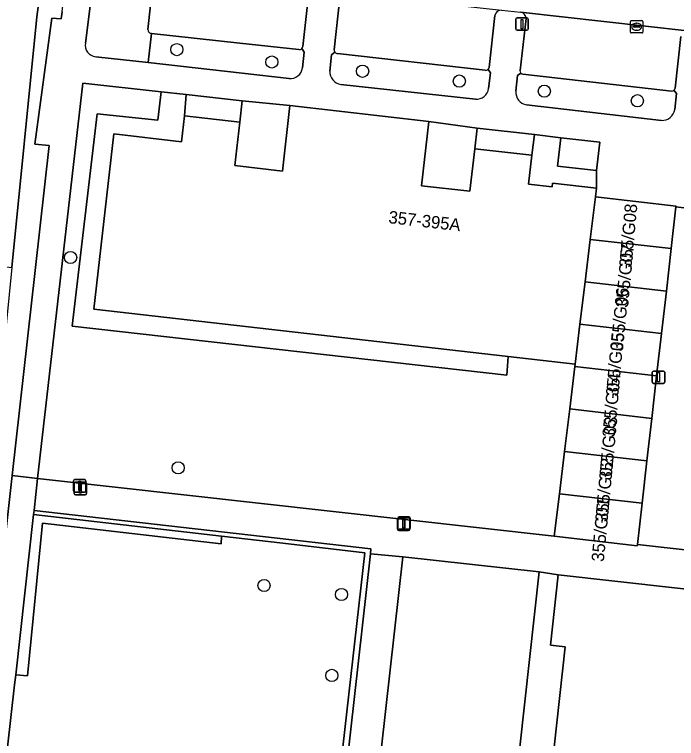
# Model space of a CAD drawing. Extents: x 161928 to 163071, y 386474 to 387428.
# Drawn here: x 162005.2 to 162058.3, y 386750.7 to 386808.8 of the extents above; entities that cross this region are included whole.
import ezdxf

# ---------------------------------------------------------------- set-up
doc = ezdxf.new("R2010")
doc.units = 0
for name, color, linetype in [('IMGEO_Berm_groen', 7, 'Continuous'), ('IMGEO_Boom', 7, 'Continuous'), ('IMGEO_Erf', 7, 'Continuous'), ('IMGEO_Groenvoorziening', 7, 'Continuous'), ('IMGEO_Haag', 7, 'Continuous'), ('IMGEO_Kolk', 7, 'Continuous'), ('IMGEO_Lichtmast', 7, 'Continuous'), ('IMGEO_Pand', 7, 'Continuous'), ('IMGEO_Pand_nummerreeks', 7, 'Continuous'), ('IMGEO_Parkeervlak_open', 7, 'Continuous'), ('IMGEO_Rijbaan_lokaal_open', 7, 'Continuous'), ('IMGEO_Voetpad_open', 7, 'Continuous')]:
    doc.layers.add(name, color=color, linetype=linetype)

msp = doc.modelspace()

# ---------------------------------------------------------------- linework, layer by layer
at = {"layer": 'IMGEO_Berm_groen'}
msp.add_lwpolyline([(162000, 386876.945), (161990.392, 386790.363), (162005.008, 386788.518), (162007.001, 386808.617), (162009.798, 386829.325)], dxfattribs=at)
at = {"layer": 'IMGEO_Boom'}
for centre in [(162018.233, 386805.998), (162025.846, 386805.003), (162033.13, 386804.262), (162040.888, 386803.474), (162047.706, 386802.66), (162055.171, 386801.897), (162009.707, 386789.308), (162018.339, 386772.436), (162025.225, 386762.991), (162031.439, 386762.26), (162030.664, 386755.77)]:
    msp.add_circle(centre, 0.489, dxfattribs=at)
at = {"layer": 'IMGEO_Erf'}
for points in [[(162016.97, 386802.618), (162016.705, 386800.327), (162011.83, 386800.848), (162009.846, 386783.804), (162044.709, 386779.862), (162044.806, 386781.365), (162011.56, 386785.17), (162013.168, 386799.23), (162018.607, 386798.607), (162018.845, 386800.686), (162018.982, 386802.396)], [(162044.512, 386725.13), (162045.14, 386730.766), (162046.333, 386730.634), (162047.268, 386739.022), (162046.075, 386739.154), (162047.261, 386749.807), (162048.454, 386749.675), (162048.49, 386750), (162049.389, 386758.073), (162048.195, 386758.205), (162048.824, 386763.85), (162047.299, 386764.081), (162045.743, 386750), (162043.01, 386725.268)]]:
    msp.add_lwpolyline(points, close=True, dxfattribs=at)
at = {"layer": 'IMGEO_Groenvoorziening'}
for points in [[(162007.994, 386798.293), (162006.852, 386798.42), (162008.208, 386808.516), (162008.959, 386808.465), (162009.031, 386809.044), (162011.288, 386829.156), (162009.798, 386829.325), (162007.001, 386808.617), (162005.008, 386788.518), (161998.505, 386722.956), (161997.23, 386714.781), (161996.045, 386706.635), (161994.485, 386698.645), (161994.672, 386692.84), (161993.174, 386677.984), (161990.334, 386655.356), (161991.413, 386650.255), (161998.872, 386716.846), (162005.028, 386771.813), (162006.873, 386788.282)], [(162050.178, 386780.75), (162044.806, 386781.365), (162044.709, 386779.862), (162009.846, 386783.804), (162011.83, 386800.848), (162016.705, 386800.327), (162016.97, 386802.618), (162010.678, 386803.312), (162007.061, 386771.581), (162048.503, 386766.944), (162048.916, 386770.347), (162049.329, 386773.751), (162049.742, 386777.154), (162050.155, 386780.557)], [(162023.281, 386800.178), (162023.483, 386801.899), (162018.982, 386802.396), (162018.845, 386800.686)], [(162046.716, 386797.515), (162046.91, 386799.189), (162042.308, 386799.694), (162042.13, 386798.04)], [(162052.172, 386798.582), (162049.03, 386798.931), (162048.771, 386796.639), (162051.904, 386796.301)], [(162021.82, 386766.942), (162006.74, 386768.689), (162005.304, 386755.813), (162006.241, 386755.742), (162007.448, 386767.992), (162021.773, 386766.325)], [(162031.554, 386750), (162033.319, 386765.609), (162026.736, 386766.372), (162021.82, 386766.942), (162021.773, 386766.325), (162007.448, 386767.992), (162006.241, 386755.742), (162005.304, 386755.813), (162005.214, 386755.021), (162004.653, 386750), (162000.921, 386716.619), (162027.442, 386713.619), (162028.943, 386726.903)], [(162045.743, 386750), (162047.299, 386764.081), (162036.361, 386765.29), (162034.645, 386750), (162032.012, 386726.545), (162033.433, 386726.38), (162043.01, 386725.268)]]:
    msp.add_lwpolyline(points, close=True, dxfattribs=at)
for points in [[(162013.294, 386825.483), (162010.901, 386806.52)], [(162015.903, 386807.622), (162016.297, 386811.299)], [(162011.721, 386805.431), (162015.927, 386804.959), (162016.195, 386807.293), (162016.142, 386807.299)], [(162028.006, 386806.003), (162023.27, 386806.52), (162016.195, 386807.293), (162015.927, 386804.959), (162027.227, 386803.691)], [(162028.307, 386804.547), (162028.431, 386805.806), (162028.255, 386806.082)], [(162030.906, 386805.784), (162030.629, 386805.593), (162030.499, 386804.276)], [(162042.95, 386804.339), (162031.119, 386805.682)], [(162043.236, 386802.887), (162043.378, 386804.136), (162043.19, 386804.405)], [(162045.82, 386804.117), (162045.564, 386803.928), (162045.434, 386802.677)], [(162057.906, 386802.677), (162045.987, 386804.016)], [(162031.388, 386803.21), (162042.177, 386802.029)], [(162058.164, 386801.204), (162058.308, 386802.479), (162058.103, 386802.744)], [(162046.266, 386801.556), (162057.102, 386800.316)]]:
    msp.add_lwpolyline(points, dxfattribs=at)
for centre, radius, start, end in [((162016.247, 386807.627), 0.344, 180.7708, 252.2275), ((162011.803, 386806.346), 0.919, 169.08634, 264.87201), ((162028.052, 386806.29), 0.291, 260.90676, 314.29849), ((162031.123, 386805.964), 0.282, 219.67341, 269.14956), ((162027.349, 386804.646), 0.963, 262.6966, 354.10356), ((162031.509, 386804.215), 1.012, 176.5187, 263.13473), ((162042.997, 386804.636), 0.301, 260.96096, 309.79155), ((162046.046, 386804.302), 0.292, 219.29109, 258.37861), ((162042.266, 386803.002), 0.977, 264.79074, 353.23793), ((162046.457, 386802.567), 1.029, 173.84566, 259.31954), ((162057.907, 386802.997), 0.32, 269.8028, 307.7637), ((162057.158, 386801.328), 1.013, 266.81003, 352.99189)]:
    msp.add_arc(centre, radius, start, end, dxfattribs=at)
at = {"layer": 'IMGEO_Haag'}
for points in [[(162023.281, 386800.178), (162023.483, 386801.899), (162018.982, 386802.396), (162018.845, 386800.686)], [(162046.716, 386797.515), (162046.91, 386799.189), (162042.308, 386799.694), (162042.13, 386798.04)], [(162052.172, 386798.582), (162049.03, 386798.931), (162048.771, 386796.639), (162051.904, 386796.301)], [(162021.82, 386766.942), (162006.74, 386768.689), (162005.304, 386755.813), (162006.241, 386755.742), (162007.448, 386767.992), (162021.773, 386766.325)]]:
    msp.add_lwpolyline(points, close=True, dxfattribs=at)
at = {"layer": 'IMGEO_Kolk'}
for p, q in [((162054.611, 386807.41), (162054.611, 386808.262)), ((162054.686, 386808.336), (162055.538, 386808.336)), ((162055.612, 386808.262), (162055.612, 386807.41)), ((162054.87, 386807.83), (162054.87, 386807.842)), ((162055.308, 386807.793), (162054.91, 386807.793)), ((162054.913, 386807.879), (162055.311, 386807.879)), ((162055.099, 386808.116), (162055.124, 386808.116)), ((162055.354, 386807.842), (162055.354, 386807.83)), ((162055.538, 386807.336), (162054.686, 386807.336)), ((162055.122, 386807.556), (162055.097, 386807.556))]:
    msp.add_line(p, q, dxfattribs=at)
for points in [[(162054.611, 386807.41), (162054.611, 386808.262)], [(162054.686, 386808.336), (162055.538, 386808.336)], [(162055.612, 386808.262), (162055.612, 386807.41)], [(162055.538, 386807.336), (162054.686, 386807.336)]]:
    msp.add_lwpolyline(points, dxfattribs=at)
for centre, radius, start, end in [((162054.688, 386808.26), 0.0765, 91.55205, 178.44795), ((162054.688, 386808.26), 0.0765, 91.55205, 178.44795), ((162055.536, 386808.26), 0.0765, 1.55205, 88.44795), ((162055.536, 386808.26), 0.0765, 1.55205, 88.44795), ((162054.91, 386807.839), 0.0403, 85.87752, 175.75265), ((162054.907, 386807.829), 0.0366, 178.93798, 274.71019), ((162055.311, 386807.836), 0.043, 264.86636, 352.45326), ((162055.315, 386807.841), 0.0386, 1.73085, 96.63898), ((162054.688, 386807.412), 0.0765, 181.55205, 268.44795), ((162054.688, 386807.412), 0.0765, 181.55205, 268.44795), ((162055.536, 386807.412), 0.0765, 271.55205, 358.44795), ((162055.536, 386807.412), 0.0765, 271.55205, 358.44795)]:
    msp.add_arc(centre, radius, start, end, dxfattribs=at)
for centre, major_axis, ratio, start_param, end_param in [((162055.098, 386807.836), (-0.387, 0.002), 0.722429, 4.712389, 7.853982), ((162055.123, 386807.836), (-0.39, 0.002), 0.717154, 1.570796, 4.712389)]:
    msp.add_ellipse(centre, major_axis=major_axis, ratio=ratio, start_param=start_param, end_param=end_param, dxfattribs=at)
at = {"layer": 'IMGEO_Lichtmast'}
for p, q in [((162045.426, 386807.652), (162045.426, 386808.452)), ((162045.426, 386808.452), (162045.426, 386807.652)), ((162045.526, 386808.552), (162046.316, 386808.552)), ((162046.316, 386808.552), (162045.526, 386808.552)), ((162046.416, 386808.452), (162046.416, 386807.652)), ((162046.416, 386807.652), (162046.416, 386808.452)), ((162046.316, 386807.552), (162045.526, 386807.552)), ((162045.526, 386807.552), (162046.316, 386807.552)), ((162056.37, 386779.302), (162056.37, 386780.102)), ((162056.37, 386780.102), (162056.37, 386779.302)), ((162056.47, 386780.202), (162057.26, 386780.202)), ((162057.26, 386780.202), (162056.47, 386780.202)), ((162057.36, 386780.102), (162057.36, 386779.302)), ((162057.36, 386779.302), (162057.36, 386780.102)), ((162057.26, 386779.202), (162056.47, 386779.202)), ((162056.47, 386779.202), (162057.26, 386779.202)), ((162009.938, 386770.583), (162009.938, 386771.383)), ((162009.938, 386771.383), (162009.938, 386770.583)), ((162009.999, 386770.373), (162009.999, 386771.173)), ((162009.999, 386771.173), (162009.999, 386770.373)), ((162010.038, 386771.483), (162010.828, 386771.483)), ((162010.828, 386771.483), (162010.038, 386771.483)), ((162010.099, 386771.273), (162010.889, 386771.273)), ((162010.889, 386771.273), (162010.099, 386771.273)), ((162010.928, 386771.383), (162010.928, 386770.583)), ((162010.928, 386770.583), (162010.928, 386771.383)), ((162010.989, 386771.173), (162010.989, 386770.373)), ((162010.989, 386770.373), (162010.989, 386771.173)), ((162010.828, 386770.483), (162010.038, 386770.483)), ((162010.038, 386770.483), (162010.828, 386770.483)), ((162010.889, 386770.273), (162010.099, 386770.273)), ((162010.099, 386770.273), (162010.889, 386770.273)), ((162035.925, 386767.512), (162035.925, 386768.312)), ((162035.925, 386768.312), (162035.925, 386767.512)), ((162035.958, 386767.597), (162035.958, 386768.397)), ((162035.958, 386768.397), (162035.958, 386767.597)), ((162036.025, 386768.412), (162036.815, 386768.412)), ((162036.815, 386768.412), (162036.025, 386768.412)), ((162036.058, 386768.497), (162036.848, 386768.497)), ((162036.848, 386768.497), (162036.058, 386768.497)), ((162036.915, 386768.312), (162036.915, 386767.512)), ((162036.915, 386767.512), (162036.915, 386768.312)), ((162036.948, 386768.397), (162036.948, 386767.597)), ((162036.948, 386767.597), (162036.948, 386768.397)), ((162036.848, 386767.497), (162036.058, 386767.497)), ((162036.058, 386767.497), (162036.848, 386767.497)), ((162036.815, 386767.412), (162036.025, 386767.412)), ((162036.025, 386767.412), (162036.815, 386767.412))]:
    msp.add_line(p, q, dxfattribs=at)
for points in [[(162045.846, 386808.427), (162045.996, 386808.427), (162045.996, 386807.677), (162045.846, 386807.677), (162045.846, 386808.427)], [(162056.79, 386780.077), (162056.94, 386780.077), (162056.94, 386779.327), (162056.79, 386779.327), (162056.79, 386780.077)], [(162010.358, 386771.358), (162010.508, 386771.358), (162010.508, 386770.608), (162010.358, 386770.608), (162010.358, 386771.358)], [(162010.419, 386771.148), (162010.569, 386771.148), (162010.569, 386770.398), (162010.419, 386770.398), (162010.419, 386771.148)], [(162036.345, 386768.287), (162036.495, 386768.287), (162036.495, 386767.537), (162036.345, 386767.537), (162036.345, 386768.287)], [(162036.378, 386768.372), (162036.528, 386768.372), (162036.528, 386767.622), (162036.378, 386767.622), (162036.378, 386768.372)]]:
    msp.add_lwpolyline(points, dxfattribs=at)
for centre, start, end in [((162045.526, 386808.452), 90, 180), ((162045.526, 386808.452), 90, 180), ((162046.316, 386808.452), 0, 90), ((162046.316, 386808.452), 360, 90), ((162045.526, 386807.652), 180, 270), ((162045.526, 386807.652), 180, 270), ((162046.316, 386807.652), 270, 0), ((162046.316, 386807.652), 270, 0), ((162056.47, 386780.102), 90, 180), ((162056.47, 386780.102), 90, 180), ((162057.26, 386780.102), 0, 90), ((162057.26, 386780.102), 360, 90), ((162056.47, 386779.302), 180, 270), ((162056.47, 386779.302), 180, 270), ((162057.26, 386779.302), 270, 0), ((162057.26, 386779.302), 270, 0), ((162010.038, 386771.383), 90, 180), ((162010.038, 386771.383), 90, 180), ((162010.099, 386771.173), 90, 180), ((162010.099, 386771.173), 90, 180), ((162010.828, 386771.383), 0, 90), ((162010.828, 386771.383), 360, 90), ((162010.889, 386771.173), 0, 90), ((162010.889, 386771.173), 360, 90), ((162010.038, 386770.583), 180, 270), ((162010.038, 386770.583), 180, 270), ((162010.099, 386770.373), 180, 270), ((162010.099, 386770.373), 180, 270), ((162010.828, 386770.583), 270, 0), ((162010.828, 386770.583), 270, 0), ((162010.889, 386770.373), 270, 0), ((162010.889, 386770.373), 270, 0), ((162036.025, 386768.312), 90, 180), ((162036.025, 386768.312), 90, 180), ((162036.058, 386768.397), 90, 180), ((162036.058, 386768.397), 90, 180), ((162036.815, 386768.312), 0, 90), ((162036.815, 386768.312), 360, 90), ((162036.848, 386768.397), 0, 90), ((162036.848, 386768.397), 360, 90), ((162036.025, 386767.512), 180, 270), ((162036.025, 386767.512), 180, 270), ((162036.058, 386767.597), 180, 270), ((162036.058, 386767.597), 180, 270), ((162036.815, 386767.512), 270, 0), ((162036.815, 386767.512), 270, 0), ((162036.848, 386767.597), 270, 0), ((162036.848, 386767.597), 270, 0)]:
    msp.add_arc(centre, 0.1, start, end, dxfattribs=at)
at = {"layer": 'IMGEO_Pand'}
for points in [[(162050.978, 386787.364), (162051.389, 386790.754), (162051.802, 386794.17), (162051.886, 386794.866), (162048.36, 386795.27), (162048.326, 386794.973), (162046.449, 386795.188), (162046.716, 386797.515), (162042.13, 386798.04), (162041.739, 386794.629), (162037.848, 386795.074), (162038.44, 386800.239), (162027.307, 386801.514), (162026.705, 386796.253), (162022.881, 386796.691), (162023.281, 386800.178), (162018.845, 386800.686), (162018.607, 386798.607), (162013.168, 386799.23), (162011.56, 386785.17), (162044.806, 386781.365), (162050.178, 386780.75), (162050.566, 386783.96)], [(162058.268, 386793.375), (162058.274, 386793.43), (162051.802, 386794.17), (162051.389, 386790.754), (162057.884, 386790.024)], [(162057.884, 386790.024), (162051.389, 386790.754), (162050.978, 386787.364), (162057.495, 386786.618)], [(162050.566, 386783.96), (162057.105, 386783.212), (162057.495, 386786.618), (162050.978, 386787.364)], [(162050.155, 386780.557), (162056.716, 386779.806), (162057.105, 386783.212), (162050.566, 386783.96), (162050.178, 386780.75)], [(162049.742, 386777.154), (162056.326, 386776.401), (162056.716, 386779.806), (162050.155, 386780.557)], [(162049.329, 386773.751), (162055.936, 386772.995), (162056.326, 386776.401), (162049.742, 386777.154)], [(162048.916, 386770.347), (162055.547, 386769.589), (162055.936, 386772.995), (162049.329, 386773.751)], [(162055.547, 386769.589), (162048.916, 386770.347), (162048.503, 386766.944), (162055.157, 386766.183), (162055.168, 386766.28)]]:
    msp.add_lwpolyline(points, close=True, dxfattribs=at)
msp.add_lwpolyline([(162062.945, 386762.278), (162048.824, 386763.85), (162048.195, 386758.205), (162049.389, 386758.073), (162048.49, 386750), (162048.454, 386749.675), (162047.261, 386749.807), (162046.075, 386739.154), (162047.268, 386739.022), (162046.333, 386730.634), (162045.14, 386730.766), (162044.512, 386725.13), (162058.594, 386723.562)], dxfattribs=at)
at = {"layer": 'IMGEO_Parkeervlak_open'}
for points in [[(162016.297, 386811.299), (162015.903, 386807.622)], [(162028.339, 386806.25), (162028.786, 386810.378)], [(162031.308, 386810.179), (162030.839, 386805.986)], [(162043.291, 386804.571), (162043.746, 386808.744)], [(162059.177, 386807.503), (162045.806, 386809.001)], [(162046.244, 386808.485), (162045.756, 386804.319)], [(162016.142, 386807.299), (162016.195, 386807.293), (162023.27, 386806.52), (162028.006, 386806.003)], [(162058.211, 386802.899), (162058.654, 386807.065)], [(162031.119, 386805.682), (162042.95, 386804.339)], [(162045.987, 386804.016), (162057.906, 386802.677)]]:
    msp.add_lwpolyline(points, dxfattribs=at)
for centre, radius, start, end in [((162044.231, 386808.667), 0.491, 84.80445, 171.02046), ((162045.736, 386808.497), 0.509, 358.60957, 82.0421), ((162016.247, 386807.627), 0.344, 180.7708, 252.2275), ((162028.052, 386806.29), 0.291, 260.90676, 314.29849), ((162028.052, 386806.289), 0.29, 314.5103, 352.35959), ((162031.122, 386805.968), 0.284, 176.32026, 220.37937), ((162031.123, 386805.964), 0.282, 219.67341, 269.14956), ((162042.997, 386804.636), 0.301, 260.96096, 309.79155), ((162042.99, 386804.64), 0.309, 310.33336, 347.03115), ((162046.047, 386804.3), 0.292, 176.27829, 218.88141), ((162046.046, 386804.302), 0.292, 219.29109, 258.37861), ((162057.907, 386802.997), 0.32, 269.8028, 307.7637), ((162057.914, 386802.991), 0.311, 307.43483, 342.82959)]:
    msp.add_arc(centre, radius, start, end, dxfattribs=at)
at = {"layer": 'IMGEO_Rijbaan_lokaal_open'}
for points in [[(162014.294, 386812.462), (162015.464, 386812.349), (162029.305, 386810.835), (162030.854, 386810.676), (162044.275, 386809.156), (162045.806, 386809.001), (162059.177, 386807.503), (162062.189, 386807.174)], [(162060.619, 386793.088), (162058.268, 386793.375), (162057.884, 386790.024), (162057.495, 386786.618), (162057.105, 386783.212), (162056.716, 386779.806), (162056.326, 386776.401), (162055.936, 386772.995), (162055.547, 386769.589), (162055.168, 386766.28), (162064.004, 386765.296), (162068.285, 386803.638), (162068.4, 386804.529)]]:
    msp.add_lwpolyline(points, dxfattribs=at)
at = {"layer": 'IMGEO_Voetpad_open'}
for points in [[(162010.901, 386806.52), (162013.294, 386825.483)], [(162028.786, 386810.378), (162028.339, 386806.25)], [(162030.839, 386805.986), (162031.308, 386810.179)], [(162009.031, 386809.044), (162008.959, 386808.465), (162008.208, 386808.516), (162006.852, 386798.42), (162007.994, 386798.293), (162006.873, 386788.282), (162005.028, 386771.813), (162007.061, 386771.581), (162010.678, 386803.312), (162016.97, 386802.618), (162018.982, 386802.396), (162023.483, 386801.899), (162027.307, 386801.514), (162038.44, 386800.239), (162042.308, 386799.694), (162046.91, 386799.189), (162049.03, 386798.931), (162052.172, 386798.582), (162051.904, 386796.301), (162051.886, 386794.866), (162051.802, 386794.17), (162058.274, 386793.43), (162058.268, 386793.375), (162060.619, 386793.088)], [(162043.746, 386808.744), (162043.291, 386804.571)], [(162045.756, 386804.319), (162046.244, 386808.485)], [(162058.654, 386807.065), (162058.211, 386802.899)], [(162028.255, 386806.082), (162028.431, 386805.806), (162028.307, 386804.547)], [(162027.227, 386803.691), (162015.927, 386804.959), (162011.721, 386805.431)], [(162030.499, 386804.276), (162030.629, 386805.593), (162030.906, 386805.784)], [(162043.19, 386804.405), (162043.378, 386804.136), (162043.236, 386802.887)], [(162045.434, 386802.677), (162045.564, 386803.928), (162045.82, 386804.117)], [(162042.177, 386802.029), (162031.388, 386803.21)], [(162058.103, 386802.744), (162058.308, 386802.479), (162058.164, 386801.204)], [(162057.102, 386800.316), (162046.266, 386801.556)], [(162004.653, 386750), (162005.214, 386755.021), (162005.304, 386755.813), (162006.74, 386768.689), (162006.777, 386769.017), (162007.061, 386771.581), (162005.028, 386771.813), (161998.872, 386716.846), (161991.413, 386650.255), (161988.931, 386628.093), (161988.105, 386628.184), (161987.456, 386622.282), (161987.333, 386614.588), (161986.323, 386614.553)], [(162064.004, 386765.296), (162055.168, 386766.28), (162055.157, 386766.183), (162048.503, 386766.944), (162007.061, 386771.581), (162006.777, 386769.017), (162033.803, 386765.933), (162033.754, 386765.523), (162036.361, 386765.29), (162047.299, 386764.081), (162048.824, 386763.85), (162062.945, 386762.278), (162065.031, 386762.071), (162068.744, 386761.57), (162068.982, 386765.015)], [(162036.361, 386765.29), (162033.754, 386765.523), (162029.566, 386728.062)], [(162031.198, 386724.615), (162032.012, 386726.545), (162034.645, 386750), (162036.361, 386765.29)]]:
    msp.add_lwpolyline(points, dxfattribs=at)
for points in [[(162023.483, 386801.899), (162023.281, 386800.178), (162022.881, 386796.691), (162026.705, 386796.253), (162027.307, 386801.514)], [(162038.44, 386800.239), (162037.848, 386795.074), (162041.739, 386794.629), (162042.13, 386798.04), (162042.308, 386799.694)], [(162046.91, 386799.189), (162046.716, 386797.515), (162046.449, 386795.188), (162048.326, 386794.973), (162048.36, 386795.27), (162051.886, 386794.866), (162051.904, 386796.301), (162048.771, 386796.639), (162049.03, 386798.931)], [(162006.777, 386769.017), (162006.74, 386768.689), (162021.82, 386766.942), (162026.736, 386766.372), (162033.319, 386765.609), (162031.554, 386750), (162028.943, 386726.903), (162029.484, 386726.918), (162029.566, 386728.062), (162033.754, 386765.523), (162033.803, 386765.933)]]:
    msp.add_lwpolyline(points, close=True, dxfattribs=at)
for centre, radius, start, end in [((162044.231, 386808.667), 0.491, 84.80445, 171.02046), ((162045.736, 386808.497), 0.509, 358.60957, 82.0421), ((162011.803, 386806.346), 0.919, 169.08634, 264.87201), ((162028.052, 386806.289), 0.29, 314.5103, 352.35959), ((162031.122, 386805.968), 0.284, 176.32026, 220.37937), ((162027.349, 386804.646), 0.963, 262.6966, 354.10356), ((162031.509, 386804.215), 1.012, 176.5187, 263.13473), ((162042.99, 386804.64), 0.309, 310.33336, 347.03115), ((162046.047, 386804.3), 0.292, 176.27829, 218.88141), ((162042.266, 386803.002), 0.977, 264.79074, 353.23793), ((162046.457, 386802.567), 1.029, 173.84566, 259.31954), ((162057.914, 386802.991), 0.311, 307.43483, 342.82959), ((162057.158, 386801.328), 1.013, 266.81003, 352.99189)]:
    msp.add_arc(centre, radius, start, end, dxfattribs=at)

# ---------------------------------------------------------------- texts
at = {"layer": 'IMGEO_Pand_nummerreeks'}
for s, rotation, p in [('357-395A', 353.47563, (162035.168, 386792.078)), ('355/G08', 84.62587, (162054.694, 386788.475)), ('355/G07', 84.62748, (162054.419, 386785.259)), ('355/G06', 84.62748, (162054.007, 386781.745)), ('355/G05', 84.62748, (162053.633, 386778.145)), ('355/G04', 84.62748, (162053.348, 386774.855)), ('355/G03', 84.62748, (162053.09, 386771.39)), ('355/G02', 84.62748, (162052.777, 386768.061)), ('355/G01', 84.62587, (162052.476, 386764.854))]:
    msp.add_text(s, height=1, rotation=rotation, dxfattribs=at).set_placement(p)

doc.saveas('drawing.dxf')
